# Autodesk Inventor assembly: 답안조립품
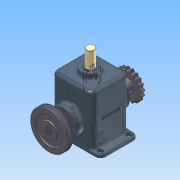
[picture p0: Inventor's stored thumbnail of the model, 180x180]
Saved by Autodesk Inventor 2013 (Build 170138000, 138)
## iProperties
Created: 2015-01
Part Number: 답안조립품
Document SubType Name: Assembly
Designer: Administrator
Mass: 8618.01 g
Surface Area: 4424.07 cm^2
Volume: 1987.46 cm^3
Density: 4.33619 g/cm^3
Author: Administrator
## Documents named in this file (15)
- C:\Users\Administrator\Documents\350106V1002\답안조립품.iam
- C:\Users\Administrator\Documents\350106V1002\본체.ipt
- C:\Users\Administrator\Documents\350106V1002\M4x0.5.ipt
- C:\Users\Administrator\Documents\350106V1002\V-벨트풀리.ipt
- C:\Users\Administrator\Documents\350106V1002\가변스프링.ipt
- C:\Users\Administrator\Documents\350106V1002\멈춤나사 M5x0.5.ipt
- C:\Users\Administrator\Documents\350106V1002\멈춤링.ipt
- C:\Users\Administrator\Documents\350106V1002\베어링 6205.ipt
- C:\Users\Administrator\Documents\350106V1002\부시.ipt
- C:\Users\Administrator\Documents\350106V1002\슬라이드.ipt
- C:\Users\Administrator\Documents\350106V1002\오일실.ipt
- C:\Users\Administrator\Documents\350106V1002\체인 스프로킷.ipt
- C:\Users\Administrator\Documents\350106V1002\커버.ipt
- C:\Users\Administrator\Documents\350106V1002\키 8x8.ipt
- C:\Users\Administrator\Documents\350106V1002\편심축.ipt
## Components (9 placed, 4 different names)
1. V-벨트풀리:1 — 플러쉬:1, 각도:1
2. 가변스프링:1
3. 5-체인 스프로킷:1 — 플러쉬:2
4. M4x0.5:2
5. M4x0.5:3
6. M4x0.5:4
7. M4x0.5:1
8. M4x0.5:5
9. M4x0.5:6
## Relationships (3: Flush 2, Angle 1)
- 플러쉬:1 [Flush]: V-벨트풀리:1
- 플러쉬:2 [Flush]: 5-체인 스프로킷:1
- 각도:1 [Angle]: V-벨트풀리:1
